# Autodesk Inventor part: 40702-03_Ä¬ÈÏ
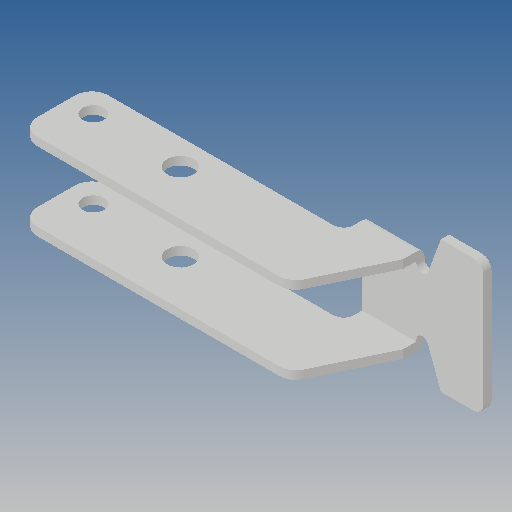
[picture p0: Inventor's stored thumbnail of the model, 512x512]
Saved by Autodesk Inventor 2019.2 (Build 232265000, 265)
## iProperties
Created: 2010-06
Part Number: 40702-03_Ä¬ÈÏ
Material: Ogólny
Document SubType Name: Modeling
Designer: CADENGINEERING4
Density: 1 g/cm^3
Appearance: Domyślna
Author: CADENGINEERING4
Revision Number: ÈÎºÎ
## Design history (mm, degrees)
feature "NONE"
node "Bryła1"
